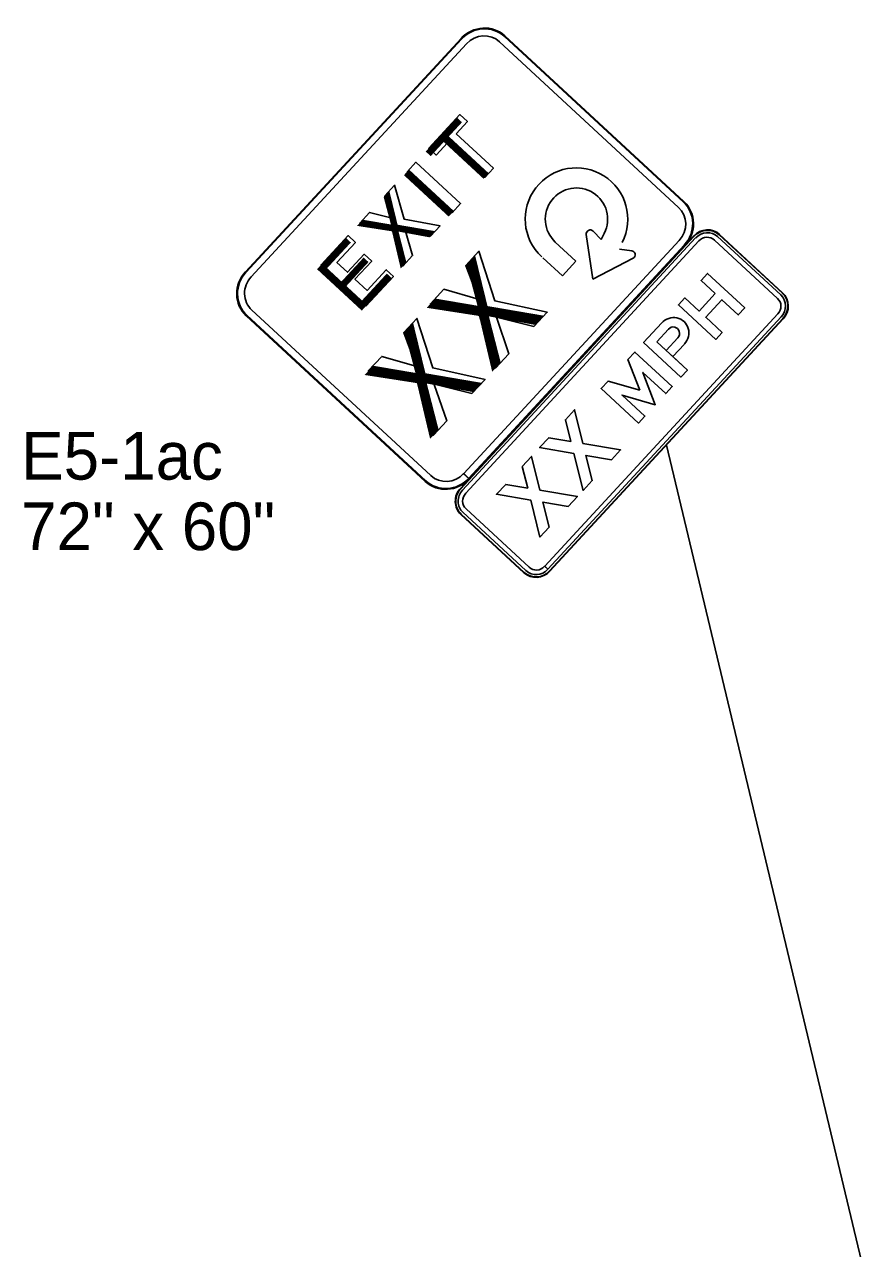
# Model space of a CAD drawing. Extents: x 571683 to 574814, y 1530838 to 1532924.
# Drawn here: x 572744.5 to 573075.6, y 1532389.3 to 1532870.9 of the extents above; entities that cross this region are included whole.
import ezdxf

# ---------------------------------------------------------------- set-up
doc = ezdxf.new("R2010")
doc.units = 0
for name, color, linetype in [('SignDetail', 7, 'Continuous'), ('SignPanel', 7, 'Continuous'), ('TextLabel', 7, 'Continuous')]:
    doc.layers.add(name, color=color, linetype=linetype)

msp = doc.modelspace()

# ---------------------------------------------------------------- linework, layer by layer
at = {"layer": 'SignDetail'}
msp.add_line((573132.85, 1532137.75), (572997.25, 1532705.45), dxfattribs=at)
at = {"layer": 'SignPanel'}
for p, q in [((572916.33, 1532865.39), (572831.46, 1532773.61)), ((572916.33, 1532865.39), (572831.46, 1532773.61)), ((572916.33, 1532865.39), (572831.46, 1532773.61)), ((572831.68, 1532773.41), (572916.55, 1532865.19)), ((572833.67, 1532771.58), (572918.53, 1532863.35)), ((572931.5, 1532864.13), (573001.99, 1532798.95)), ((572933.41, 1532866.19), (573003.9, 1532801.02)), ((573004.11, 1532801.25), (572933.62, 1532866.42)), ((573004.11, 1532801.25), (572933.62, 1532866.42)), ((573004.11, 1532801.25), (572933.62, 1532866.42)), ((572968.34, 1532789.61), (572971.5, 1532786.34)), ((573007.91, 1532787.68), (572916.11, 1532688.39)), ((573007.91, 1532787.68), (572916.11, 1532688.39)), ((572916.23, 1532688.27), (573008.04, 1532787.56)), ((573008.71, 1532786.93), (572916.91, 1532687.65)), ((573002.23, 1532785.96), (572917.39, 1532694.2)), ((572918.19, 1532686.46), (573010, 1532785.74)), ((572953.46, 1532785.32), (572961.59, 1532777.8)), ((572968.29, 1532770.66), (572965.65, 1532788.28)), ((572971.5, 1532786.34), (572972.72, 1532788.74)), ((573016.12, 1532786.11), (573040.95, 1532763.15)), ((573042.19, 1532764.49), (573017.36, 1532787.45)), ((573018.01, 1532788.15), (573042.84, 1532765.2)), ((573042.96, 1532765.33), (573018.14, 1532788.28)), ((573042.96, 1532765.33), (573018.14, 1532788.28)), ((573004.21, 1532784.12), (572919.35, 1532692.35)), ((572919.57, 1532692.14), (573004.43, 1532783.92)), ((572919.57, 1532692.15), (573004.43, 1532783.92)), ((572919.59, 1532692.17), (573004.43, 1532783.92)), ((572978.76, 1532782.57), (572983.53, 1532781.91)), ((572956.22, 1532771.98), (572948.49, 1532779.13)), ((572984.05, 1532778.96), (572968.29, 1532770.66)), ((572831.79, 1532756.29), (572902.27, 1532691.11)), ((572831.79, 1532756.29), (572902.27, 1532691.11)), ((572831.79, 1532756.29), (572902.27, 1532691.11)), ((572902.49, 1532691.34), (572832, 1532756.52)), ((572904.39, 1532693.41), (572833.91, 1532758.58)), ((573041.06, 1532757.02), (572949.27, 1532657.75)), ((572950.56, 1532656.56), (573042.35, 1532755.83)), ((573043.02, 1532755.21), (572951.22, 1532655.92)), ((572951.35, 1532655.8), (573043.15, 1532755.09)), ((572951.35, 1532655.81), (573043.15, 1532755.09)), ((572993.4, 1532746.06), (572998, 1532751.03)), ((572993.4, 1532746.06), (572998, 1532751.03)), ((572993.4, 1532746.06), (572998, 1532751.03)), ((572999.72, 1532740.22), (573004.31, 1532745.19)), ((572919.57, 1532692.14), (572917.37, 1532694.18)), ((572917.39, 1532694.2), (572919.59, 1532692.17)), ((572919.57, 1532692.14), (572919.35, 1532692.35)), ((572919.35, 1532692.35), (572919.57, 1532692.15)), ((572917.07, 1532678.99), (572941.9, 1532656.03)), ((572943.13, 1532657.37), (572918.31, 1532680.33)), ((572916.3, 1532678.15), (572941.12, 1532655.19)), ((572916.3, 1532678.15), (572941.12, 1532655.19)), ((572941.25, 1532655.33), (572916.42, 1532678.28)), ((572950.54, 1532656.55), (572949.26, 1532657.73)), ((572949.27, 1532657.75), (572950.56, 1532656.56)), ((572951.35, 1532655.8), (572951.22, 1532655.92)), ((572951.22, 1532655.92), (572951.35, 1532655.81))]:
    msp.add_line(p, q, dxfattribs=at)
for points in [[(572914.37, 1532827.94), (572929.06, 1532814.36), (572925.74, 1532810.76), (572911.05, 1532824.35), (572906.59, 1532819.52), (572903.66, 1532822.23), (572915.92, 1532835.49), (572918.85, 1532832.78), (572914.37, 1532827.94)], [(572912.86, 1532796.84), (572895.24, 1532813.13), (572898.56, 1532816.72), (572916.18, 1532800.43), (572912.86, 1532796.84)], [(572904.3, 1532787.58), (572894.5, 1532789.63), (572894.45, 1532789.58), (572897.27, 1532779.98), (572893.46, 1532775.85), (572889.69, 1532790.16), (572876.45, 1532792.8), (572880.32, 1532797), (572889.23, 1532794.72), (572889.28, 1532794.77), (572886.4, 1532803.56), (572890.19, 1532807.67), (572893.96, 1532794.28), (572908.1, 1532791.69), (572904.3, 1532787.58)], [(572878.88, 1532760.09), (572861.26, 1532776.38), (572871.86, 1532787.84), (572874.77, 1532785.15), (572867.49, 1532777.28), (572871.67, 1532773.42), (572878.25, 1532780.54), (572881.16, 1532777.85), (572874.58, 1532770.73), (572879.38, 1532766.29), (572886.89, 1532774.42), (572889.72, 1532771.81), (572878.88, 1532760.09)], [(572945.06, 1532752.1), (572930.3, 1532755.82), (572930.25, 1532755.76), (572935.13, 1532741.36), (572929.9, 1532735.71), (572923.61, 1532756.48), (572904.28, 1532761.03), (572909.54, 1532766.72), (572923.03, 1532762.85), (572923.15, 1532762.99), (572918.22, 1532776.11), (572923.39, 1532781.7), (572929.63, 1532762.25), (572950.25, 1532757.72), (572945.06, 1532752.1)], [(572961.59, 1532777.8), (572956.22, 1532771.98)], [(572920.62, 1532725.67), (572905.86, 1532729.39), (572905.81, 1532729.33), (572910.69, 1532714.93), (572905.46, 1532709.28), (572899.17, 1532730.05), (572879.84, 1532734.6), (572885.1, 1532740.29), (572898.58, 1532736.42), (572898.71, 1532736.56), (572893.78, 1532749.68), (572898.95, 1532755.26), (572905.19, 1532735.82), (572925.81, 1532731.29), (572920.62, 1532725.67)], [(572995.36, 1532753.48), (572988.21, 1532745.75), (573002.9, 1532732.17), (573005.44, 1532734.93), (572999.72, 1532740.22)], [(572995.36, 1532753.48), (572988.21, 1532745.75), (573002.9, 1532732.17), (573005.44, 1532734.93), (572993.4, 1532746.06)], [(572995.36, 1532753.48), (572988.21, 1532745.75), (573002.9, 1532732.17), (573005.44, 1532734.93), (572993.4, 1532746.06)], [(573001.67, 1532747.64), (572997.07, 1532742.67), (572993.4, 1532746.06)], [(573001.67, 1532747.64), (572997.07, 1532742.67), (572999.72, 1532740.22), (573004.31, 1532745.19)], [(573001.67, 1532747.64), (572997.07, 1532742.67), (572999.72, 1532740.22), (573004.31, 1532745.19)]]:
    msp.add_lwpolyline(points, dxfattribs=at)
for points in [[(573016.4, 1532765.04), (573010.03, 1532758.16), (573004.45, 1532763.32), (573001.91, 1532760.56), (573016.59, 1532746.99), (573019.14, 1532749.74), (573012.68, 1532755.71), (573019.04, 1532762.6), (573025.5, 1532756.62), (573028.05, 1532759.38), (573013.36, 1532772.95), (573010.82, 1532770.2)], [(573016.4, 1532765.04), (573010.03, 1532758.16), (573004.45, 1532763.32), (573001.91, 1532760.56), (573016.59, 1532746.99), (573019.14, 1532749.74), (573012.68, 1532755.71), (573019.04, 1532762.6), (573025.5, 1532756.62), (573028.05, 1532759.38), (573013.36, 1532772.95), (573010.82, 1532770.2)], [(573016.4, 1532765.04), (573010.03, 1532758.16), (573004.45, 1532763.32), (573001.91, 1532760.56), (573016.59, 1532746.99), (573019.14, 1532749.74), (573012.68, 1532755.71), (573019.04, 1532762.6), (573025.5, 1532756.62), (573028.05, 1532759.38), (573013.36, 1532772.95), (573010.82, 1532770.2)], [(572986.67, 1532726.98), (572982.05, 1532739.08), (572984.79, 1532742.05), (572999.47, 1532728.47), (572996.93, 1532725.72), (572987.97, 1532734), (572992.83, 1532721.28), (572979.77, 1532725.13), (572988.72, 1532716.85), (572986.18, 1532714.09), (572971.49, 1532727.67), (572974.24, 1532730.64)], [(572986.67, 1532726.98), (572982.05, 1532739.08), (572984.79, 1532742.05), (572999.47, 1532728.47), (572996.93, 1532725.72), (572987.97, 1532734), (572992.83, 1532721.28), (572979.77, 1532725.13), (572988.72, 1532716.85), (572986.18, 1532714.09), (572971.49, 1532727.67), (572974.24, 1532730.64)], [(572986.67, 1532726.98), (572982.05, 1532739.08), (572984.79, 1532742.05), (572999.47, 1532728.47), (572996.93, 1532725.72), (572987.97, 1532734), (572992.83, 1532721.28), (572979.77, 1532725.13), (572988.72, 1532716.85), (572986.18, 1532714.09), (572971.49, 1532727.67), (572974.24, 1532730.64)], [(572975.55, 1532699.66), (572965.53, 1532701.35), (572968, 1532691.49), (572964.39, 1532687.59), (572960.74, 1532702.16), (572947.28, 1532704.43), (572950.89, 1532708.33), (572959.56, 1532706.87), (572957.42, 1532715.4), (572961.03, 1532719.3), (572964.35, 1532706.06), (572979.16, 1532703.56)], [(572975.55, 1532699.66), (572965.53, 1532701.35), (572968, 1532691.49), (572964.39, 1532687.59), (572960.74, 1532702.16), (572947.28, 1532704.43), (572950.89, 1532708.33), (572959.56, 1532706.87), (572957.42, 1532715.4), (572961.03, 1532719.3), (572964.35, 1532706.06), (572979.16, 1532703.56)], [(572975.55, 1532699.66), (572965.53, 1532701.35), (572968, 1532691.49), (572964.39, 1532687.59), (572960.74, 1532702.16), (572947.28, 1532704.43), (572950.89, 1532708.33), (572959.56, 1532706.87), (572957.42, 1532715.4), (572961.03, 1532719.3), (572964.35, 1532706.06), (572979.16, 1532703.56)], [(572958.57, 1532681.3), (572948.55, 1532682.99), (572951.02, 1532673.13), (572947.41, 1532669.23), (572943.76, 1532683.8), (572930.3, 1532686.07), (572933.91, 1532689.97), (572942.58, 1532688.51), (572940.44, 1532697.04), (572944.05, 1532700.94), (572947.37, 1532687.7), (572962.18, 1532685.2)], [(572958.57, 1532681.3), (572948.55, 1532682.99), (572951.02, 1532673.13), (572947.41, 1532669.23), (572943.76, 1532683.8), (572930.3, 1532686.07), (572933.91, 1532689.97), (572942.58, 1532688.51), (572940.44, 1532697.04), (572944.05, 1532700.94), (572947.37, 1532687.7), (572962.18, 1532685.2)], [(572958.57, 1532681.3), (572948.55, 1532682.99), (572951.02, 1532673.13), (572947.41, 1532669.23), (572943.76, 1532683.8), (572930.3, 1532686.07), (572933.91, 1532689.97), (572942.58, 1532688.51), (572940.44, 1532697.04), (572944.05, 1532700.94), (572947.37, 1532687.7), (572962.18, 1532685.2)]]:
    msp.add_lwpolyline(points, close=True, dxfattribs=at)
for centre, radius, start, end in [((572961.79, 1532794.33), 20.19, 332.8783, 227.2413), ((572961.79, 1532794.33), 12.27, 332.8783, 227.2413), ((572967.21, 1532788.51), 1.57, 44.0877, 188.5128), ((572983.32, 1532780.36), 1.57, 297.7841, 82.2092)]:
    msp.add_arc(centre, radius, start, end, dxfattribs=at)
for centre, major_axis, ratio, start_param, end_param in [((572925.14, 1532857.24), (8.49, 9.18), 0.96, 0, 1.570796), ((572925.14, 1532857.24), (8.49, 9.18), 0.96, 0, 1.570796), ((572925.14, 1532857.24), (8.49, 9.18), 0.96, 0, 1.570796), ((572925.14, 1532857.24), (8.27, 8.95), 0.96, 0, 1.570796), ((572925.14, 1532857.24), (6.36, 6.88), 0.96, 0, 1.570796), ((572995.62, 1532792.07), (8.27, 8.95), 0.96, 4.712389, 6.283185), ((572995.62, 1532792.07), (8.49, 9.18), 0.96, 4.712389, 6.283185), ((572995.62, 1532792.07), (8.49, 9.18), 0.96, 4.712389, 6.283185), ((572995.62, 1532792.07), (8.49, 9.18), 0.96, 4.712389, 6.283185), ((572995.62, 1532792.07), (6.36, 6.88), 0.96, 4.712389, 6.283185), ((573013.12, 1532782.86), (5.02, 5.43), 0.96, 0, 1.570796), ((573013.12, 1532782.86), (5.02, 5.43), 0.96, 0, 1.570796), ((573013.12, 1532782.86), (4.89, 5.29), 0.96, 0, 1.570796), ((573013.12, 1532782.86), (4.24, 4.59), 0.96, 0, 1.570796), ((573013.12, 1532782.86), (3.01, 3.25), 0.96, 0, 1.570796), ((572840.27, 1532765.47), (8.49, 9.18), 0.96, 1.570796, 3.141593), ((572840.27, 1532765.47), (8.49, 9.18), 0.96, 1.570796, 3.141593), ((572840.27, 1532765.47), (8.49, 9.18), 0.96, 1.570796, 3.141593), ((572840.27, 1532765.47), (8.27, 8.95), 0.96, 1.570796, 3.141593), ((572840.27, 1532765.47), (6.36, 6.88), 0.96, 1.570796, 3.141593), ((573037.94, 1532759.9), (3.01, 3.25), 0.96, 4.712389, 6.283185), ((573037.94, 1532759.9), (4.24, 4.59), 0.96, 4.712389, 6.283185), ((573037.94, 1532759.9), (4.89, 5.29), 0.96, 4.712389, 6.283185), ((573037.94, 1532759.9), (5.02, 5.43), 0.96, 4.712389, 6.283185), ((573037.94, 1532759.9), (5.02, 5.43), 0.96, 4.712389, 6.283185), ((572999.83, 1532749.34), (4.31, 4.67), 0.960006, 4.712389, 7.853982), ((572999.83, 1532749.34), (4.31, 4.67), 0.960006, 4.712389, 7.853982), ((572999.83, 1532749.34), (4.31, 4.67), 0.960006, 4.712389, 7.853982), ((572999.83, 1532749.34), (1.77, 1.91), 0.960006, 4.712389, 7.853982), ((572999.83, 1532749.34), (1.77, 1.91), 0.960006, 4.712389, 7.853982), ((572999.83, 1532749.34), (1.77, 1.91), 0.960006, 4.712389, 7.853982), ((572910.76, 1532700.29), (6.36, 6.88), 0.96, 3.141593, 4.712389), ((572910.76, 1532700.29), (8.49, 9.18), 0.96, 3.141593, 4.712389), ((572910.76, 1532700.29), (8.49, 9.18), 0.96, 3.141593, 4.712389), ((572910.76, 1532700.29), (8.49, 9.18), 0.96, 3.141593, 4.712389), ((572910.76, 1532700.29), (8.27, 8.95), 0.96, 3.141593, 4.712389), ((572921.31, 1532683.58), (5.02, 5.43), 0.96, 1.570796, 3.141593), ((572921.31, 1532683.58), (5.02, 5.43), 0.96, 1.570796, 3.141593), ((572921.31, 1532683.58), (4.89, 5.29), 0.96, 1.570796, 3.141593), ((572921.31, 1532683.58), (4.24, 4.59), 0.96, 1.570796, 3.141593), ((572921.31, 1532683.58), (3.01, 3.25), 0.96, 1.570796, 3.141593), ((572946.14, 1532660.62), (5.02, 5.43), 0.96, 3.141593, 4.712389), ((572946.14, 1532660.62), (5.02, 5.43), 0.96, 3.141593, 4.712389), ((572946.14, 1532660.62), (4.89, 5.29), 0.96, 3.141593, 4.712389), ((572946.14, 1532660.62), (4.24, 4.59), 0.96, 3.141593, 4.712389), ((572946.14, 1532660.62), (3.01, 3.25), 0.96, 3.141593, 4.712389)]:
    msp.add_ellipse(centre, major_axis=major_axis, ratio=ratio, start_param=start_param, end_param=end_param, dxfattribs=at)

# ---------------------------------------------------------------- texts
for s, height, p in [('T', 24, (572919.57, 1532804.1)), ('T', 24, (572919.57, 1532804.1)), ('I', 24, (572909.46, 1532793.16)), ('I', 24, (572909.46, 1532793.16)), ('X', 24, (572892.1, 1532774.38)), ('X', 24, (572892.1, 1532774.38)), ('E', 24, (572875.48, 1532756.41)), ('E', 24, (572875.48, 1532756.41)), ('X', 36, (572927.86, 1532733.5)), ('X', 36, (572927.86, 1532733.5)), ('X', 36, (572903.42, 1532707.07)), ('X', 36, (572903.42, 1532707.07))]:
    msp.add_text(s, height=height, rotation=47.2413, dxfattribs=at).set_placement(p)
at = {"layer": 'TextLabel'}
for s, p in [('E5-1ac', (572743.18, 1532691.84)), ('72" x 60"', (572743.18, 1532664.1))]:
    msp.add_text(s, height=18.74, dxfattribs=at).set_placement(p)

doc.saveas('drawing.dxf')
